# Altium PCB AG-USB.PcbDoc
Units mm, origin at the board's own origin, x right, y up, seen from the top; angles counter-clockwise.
Board outline 22 x 85.18 mm, 2 copper layers (Top Layer, Bottom Layer), stack 1.571 mm thick; 10 components, 8 nets, 24 pads, 0 vias.
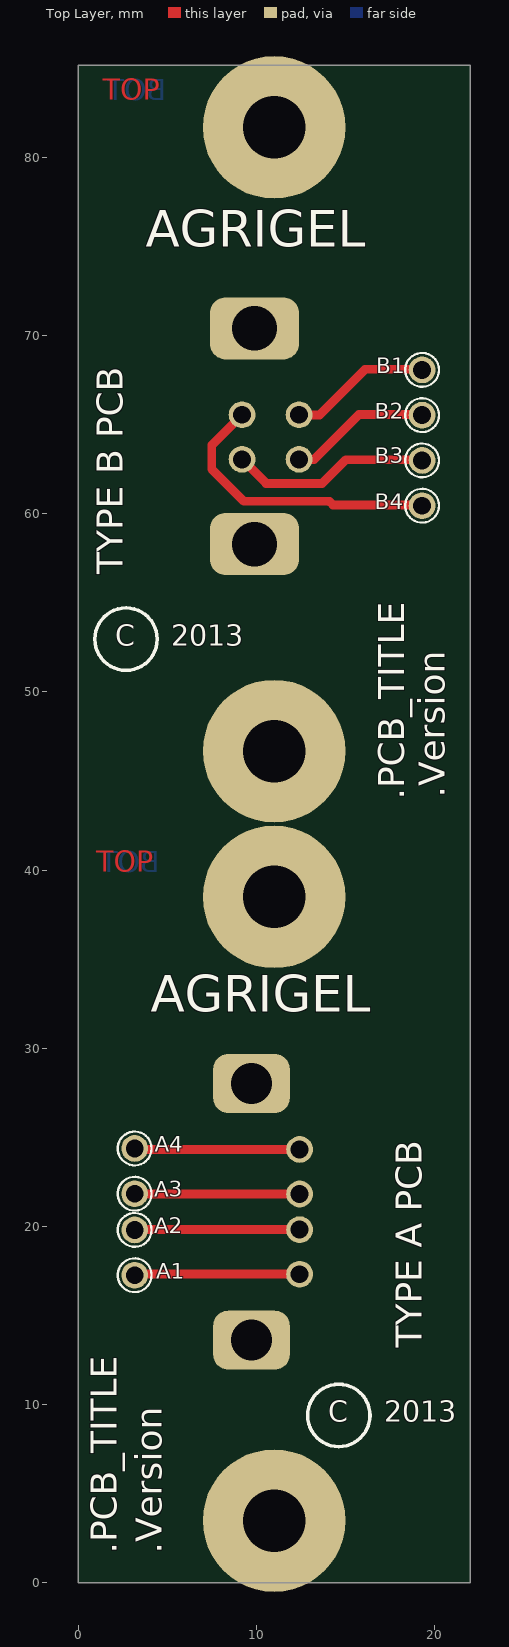
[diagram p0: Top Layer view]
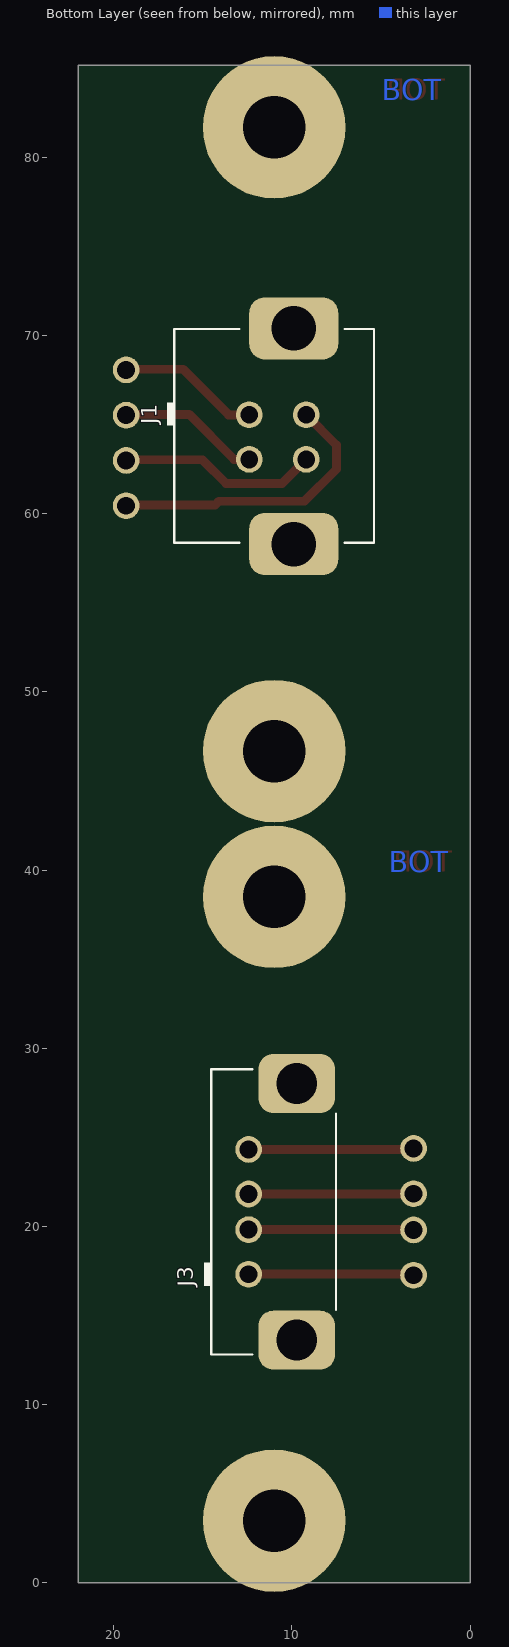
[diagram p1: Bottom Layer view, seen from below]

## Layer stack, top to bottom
Top Layer: signal copper 0.0356
Dielectric: prepreg 1.5, FR-4, Dk 4.2
Bottom Layer: signal copper 0.0356

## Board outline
0,0 0,85.18 22,85.18 22,0

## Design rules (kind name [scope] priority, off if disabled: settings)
Clearance [All] p1: gap=0.17
FabricationTestPointUsage TestPointUsage [All] p1: valid=0 allowmultiple=FALSE
FabricationTestpoint Testpoint [All] p1: side=3 testpointundercomponent=TRUE minsize=1.016 maxsize=2.54 preferedsize=1.524 minholesize=0 maxholesize=1.016 preferedholesize=0.813 testpointgrid=0.025 allowsidetop=TRUE allowsidebottom=TRUE usegrid=TRUE gridtolerance=0
HoleSize [All] p1: absolutevalues=TRUE maxlimit=5 minlimit=0.25 maxpercent=80.000 minpercent=20.000
PlaneClearance [All] p1: clearance=0.5
PolygonConnect PolygonConnectVia [All vs isvia] p1: connectstyle=Direct reliefconductorwidth=0.25 reliefentries=4 polygonreliefangle="90 Angle" airgapwidth=0.254
PolygonConnect [All] p2: connectstyle=Relief reliefconductorwidth=0.4 reliefentries=4 polygonreliefangle="90 Angle" airgapwidth=0.254
RoutingCorners [All] p1: cornerstyle=45-Degree minsetback=2.5 maxsetback=2.5
RoutingVias [All] p1: holewidth=0.3 width=0.7 viastyle="Through Hole" minholewidth=0.3 minwidth=0.7 maxholewidth=0.3 maxwidth=0.7
SilkToSolderMaskClearance SilkscreenOverComponentPads [IsPad] p1: minsilkscreentomaskgap=0.254 clearancetoexposedcopper=TRUE
SolderMaskExpansion [All] p1: expansion=0.05
Width "Width_High Power" [InNetClass('High Power')] p1: maxlimit=1.5 minlimit=0.5 preferedwidth=1
Width Width_Power [InNetClass('Power')] p2: maxlimit=1 minlimit=0.3 preferedwidth=0.5
Width [All] p3: maxlimit=2 minlimit=0.2 preferedwidth=0.2
22 further rules are at their usual default settings.

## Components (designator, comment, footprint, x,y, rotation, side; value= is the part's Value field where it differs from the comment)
A1 "Hole-1.5x3.0mm" TP-THP-1.0mm 3.175,17.272 r0 top
A2 "Hole-1.5x3.0mm" TP-THP-1.0mm 3.175,19.812 r0 top
A3 "Hole-1.5x3.0mm" TP-THP-1.0mm 3.175,21.844 r0 top
A4 "Hole-1.5x3.0mm" TP-THP-1.0mm 3.175,24.384 r0 top
B1 "Hole-1.5x3.0mm" TP-THP-1.0mm 19.304,68.072 r0 top
B2 "Hole-1.5x3.0mm" TP-THP-1.0mm 19.304,65.532 r0 top
B3 "Hole-1.5x3.0mm" TP-THP-1.0mm 19.304,62.992 r0 top
B4 "Hole-1.5x3.0mm" TP-THP-1.0mm 19.304,60.452 r0 top
J1 "USB-B-S-F-B-VT" USB-B-S-X-X-VT 11.2,64.3 r0 bottom
J3 "USB-A-S-F-B-VT" USB-A-S-X-X-VT-X 12.43,20.828 r0 bottom

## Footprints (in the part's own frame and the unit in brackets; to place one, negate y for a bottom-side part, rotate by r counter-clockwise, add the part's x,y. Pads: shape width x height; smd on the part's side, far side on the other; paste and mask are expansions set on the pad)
TP-THP-1.0mm [mm] "Test Point, THP, 1.0mm"
  round 1.5 hole 1 paste-1 mask+0.05: 1(0,0)
  silkscreen extent -0.95,-0.95 0.95,0.95, body extent -0.7,-0.7 0.7,0.7, height 0.1
USB-A-S-X-X-VT-X [mm] "USB-A-S-X-X-VT-X 7.0x14.5mm"
  round 1.5 hole 1: 1(0,3.5) 2(0,1) 3(0,-1) 4(0,-3.5)
  rrect50% 4.3x3.3 hole 2.3: M1(-2.7,7.2) M2(-2.7,-7.2)
  silkscreen extent -4.9,-8 2.5,8, body extent -4.85,-8 2.1,8, height 14.9
USB-B-S-X-X-VT [mm] "USB-B-S-X-X-VT 11.0x12.0mm"
  round 1.499 hole 1: 1(1.2,-1.25) 2(1.2,1.25) 3(-2,1.25) 4(-2,-1.25)
  rrect50% 5.004x3.48 hole 2.5: M1(-1.3,6) M2(-1.3,-6.1)
  silkscreen extent -5.8,-6.07 5.8,5.93, body extent -5.75,-7.39 5.35,7.35, height 16.15

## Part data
A1 A2 A3 A4 B1 B2 B3 B4: library part Hole-1.0mm_H, "Hole 1.0mm"
J1: "Connector USB B Vertical Top Entry"
J3: "Connector USB A Vertical Top Entry"

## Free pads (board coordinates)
  round 8 hole 3.5: 0(11,3.5) 0(11,81.68) 1(11,38.5) 1(11,46.68)

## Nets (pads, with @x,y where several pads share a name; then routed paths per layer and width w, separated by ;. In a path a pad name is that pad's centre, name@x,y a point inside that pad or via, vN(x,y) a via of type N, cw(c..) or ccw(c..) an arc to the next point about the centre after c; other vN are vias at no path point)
NetA1_1: A1.1 J3.1 | length 9.3
  Top Layer w0.5: A1.1@3.175,17.145 3.358,17.328 J3.1
NetA2_1: A2.1 J3.2 | length 9.3
  Top Layer w0.5: A2.1@3.175,19.685 3.318,19.828 J3.2
NetA3_1: A3.1 J3.3 | length 9.1
  Top Layer w0.5: A3.1@3.286,21.828 J3.3
NetA4_1: A4.1 J3.4 | length 9.4
  Top Layer w0.5: A4.1@3.175,24.765 3.612,24.328 J3.4
NetB1_1: B1.1 J1.1 | length 7.8
  Top Layer w0.5: J1.1 13.55,65.55 16.11,68.11 B1.1@19.139,68.11
NetB2_1: B2.1 J1.2 | length 7.9
  Top Layer w0.5: J1.2 13.25,63.05 15.77,65.57 B2.1@19.266,65.57
NetB3_1: B3.1 J1.3 | length 11.2
  Top Layer w0.5: J1.3 10.55,61.7 13.7,61.7 15.03,63.03 B3.1@19.266,63.03
NetB4_1: B4.1 J1.4 | length 16.4
  Top Layer w0.5: J1.4 7.5,63.85 7.5,62.5 9.3,60.7 14.1,60.7 14.31,60.49 B4.1@19.266,60.49
pads on no net: J1.M1 J1.M2 J3.M1 J3.M2

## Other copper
Top Layer:
  text "TOP" at 1.386,82.831 h2
  text "TOP" at 1.005,39.524 h2
Bottom Layer:
  text "BOT" at 4.953,82.804 h2
  text "BOT" at 4.572,39.497 h2

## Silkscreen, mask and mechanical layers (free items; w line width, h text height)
Top Overlay:
  circle w0.2: c2.691,52.963 r1.75
  circle w0.2: c14.629,9.402 r1.75
  text "AGRIGEL" at 3.81,74.295 h3.5
  text "TYPE B PCB" at 3,56.6 h2.54 r90
  text "C    2013" at 2.096,52.204 h2
  text ".Version" at 21.082,44.069 h2.54 r90
  text ".PCB_TITLE" at 18.796,43.942 h2.54 r90
  text "AGRIGEL" at 4.064,31.369 h3.5
  text "TYPE A PCB" at 19.796,13.208 h2.54 r90
  text "C    2013" at 14.034,8.643 h2
  text ".PCB_TITLE" at 2.667,1.651 h2.54 r90
  text ".Version" at 5.207,1.651 h2.54 r90
Board:
  the board outline again, w0.051
Mechanical 15:
  lines w0.051: 0,42.6 22.8,42.6 ; 4.5,3.5 17.5,3.5 ; 4.5,81.68 17.5,81.68 ; 8,38.5 14,38.5 ; 8,46.68 14,46.68 ; 11,0 11,42 ; 11,43.18 11,85.18 ; 0,0 22,0 22,42 0,42 0,0 ; 0,43.18 22,43.18 22,85.18 0,85.18 0,43.18
  text "V-Score" at 25,42.8 h1.52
